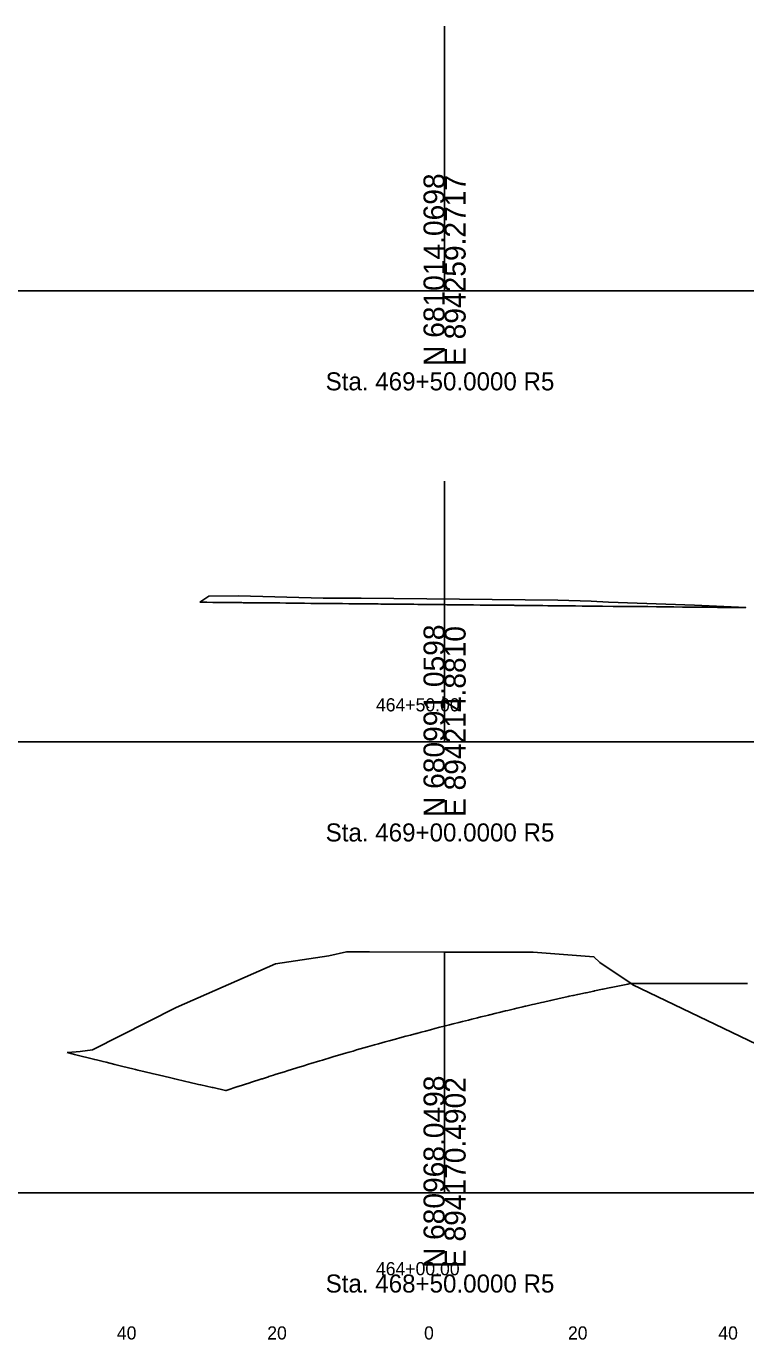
# Model space of a CAD drawing. Extents: x 21059 to 22955, y 6470 to 17494.
# Drawn here: x 21589.2 to 21684.9, y 9235.3 to 9410 of the extents above; entities that cross this region are included whole.
import ezdxf

# ---------------------------------------------------------------- set-up
doc = ezdxf.new("R2010")
doc.units = 0
for name, color, linetype in [('ASPHALT_19MM2', 7, 'Continuous'), ('Draft_XS_Text', 7, 'Continuous'), ('DTM CONTOURS_MAJOR', 7, 'Continuous'), ('SLOPE_STAKES_FILL', 7, 'Continuous'), ('X_PROFILES_1', 7, 'Continuous'), ('XS_SHEET_EW_TX_VOLUME', 7, 'Continuous')]:
    doc.layers.add(name, color=color, linetype=linetype)

msp = doc.modelspace()

# ---------------------------------------------------------------- linework, layer by layer
at = {"layer": 'DTM CONTOURS_MAJOR'}
for p, q in [((21644.84, 9374.84), (21644.84, 9410.02)), ((21494.84, 9374.84), (21644.84, 9374.84)), ((21644.84, 9374.84), (21794.84, 9374.84)), ((21644.84, 9314.84), (21644.84, 9349.53)), ((21494.84, 9314.84), (21644.84, 9314.84)), ((21644.84, 9314.84), (21794.84, 9314.84)), ((21644.84, 9254.84), (21644.84, 9286.89)), ((21494.84, 9254.84), (21644.84, 9254.84)), ((21644.84, 9254.84), (21794.84, 9254.84))]:
    msp.add_line(p, q, dxfattribs=at)
at = {"layer": 'XS_SHEET_EW_TX_VOLUME'}
for points in [[(21612.29, 9333.41), (21613.5, 9334.2), (21617.44, 9334.24), (21628.71, 9333.94), (21633.75, 9333.94), (21659.9, 9333.67), (21664.35, 9333.55), (21666.63, 9333.43), (21678.1, 9333.04), (21684.9, 9332.72), (21684.9, 9332.69), (21684.87, 9332.69), (21682.28, 9332.71), (21681.12, 9332.73), (21679.95, 9332.74), (21678.79, 9332.75), (21677.63, 9332.76), (21676.47, 9332.77), (21675.32, 9332.78), (21674.16, 9332.8), (21673.01, 9332.81), (21671.86, 9332.82), (21670.71, 9332.83), (21669.56, 9332.84), (21668.41, 9332.85), (21667.27, 9332.86), (21665.84, 9332.88), (21664.99, 9332.89), (21664.07, 9332.9), (21663.15, 9332.9), (21662.24, 9332.91), (21661.7, 9332.92), (21661.32, 9332.92), (21660.42, 9332.93), (21660.41, 9332.93), (21659.5, 9332.94), (21659.15, 9332.94), (21658.59, 9332.95), (21657.9, 9332.96), (21657.68, 9332.96), (21656.77, 9332.97), (21656.65, 9332.97), (21656.09, 9332.98), (21655.87, 9332.98), (21655.42, 9332.98), (21654.96, 9332.99), (21654.2, 9332.99), (21654.06, 9333), (21653.16, 9333), (21652.99, 9333.01), (21652.26, 9333.01), (21651.79, 9333.02), (21651.63, 9333.02), (21651.36, 9333.02), (21651, 9333.03), (21650.6, 9333.03), (21650.47, 9333.03), (21649.58, 9333.04), (21648.69, 9333.05), (21647.8, 9333.06), (21646.91, 9333.07), (21646.03, 9333.08), (21645.97, 9333.08), (21645.15, 9333.08), (21644.83, 9333.09), (21644.27, 9333.09), (21643.8, 9333.1), (21643.71, 9333.1), (21643.4, 9333.1), (21643.13, 9333.1), (21642.53, 9333.11), (21642.52, 9333.11), (21641.64, 9333.12), (21641.28, 9333.12), (21640.76, 9333.13), (21640.05, 9333.13), (21639.87, 9333.14), (21638.99, 9333.15), (21638.82, 9333.15), (21638.1, 9333.15), (21637.61, 9333.16), (21637.22, 9333.16), (21637.14, 9333.16), (21636.4, 9333.17), (21636.36, 9333.17), (21636.02, 9333.18), (21635.51, 9333.18), (21635.23, 9333.18), (21634.66, 9333.19), (21634.14, 9333.19), (21633.81, 9333.2), (21632.96, 9333.21), (21632.11, 9333.21), (21631.26, 9333.22), (21630.71, 9333.23), (21630.42, 9333.23), (21629.57, 9333.24), (21628.72, 9333.25), (21627.88, 9333.26), (21627.05, 9333.26), (21626.21, 9333.27), (21625.38, 9333.28), (21624.56, 9333.29), (21624.21, 9333.29), (21623.73, 9333.3), (21622.91, 9333.31), (21622.08, 9333.31), (21622.06, 9333.31), (21621.34, 9333.32), (21621.27, 9333.32), (21620.46, 9333.33), (21620.13, 9333.33), (21619.65, 9333.34), (21618.85, 9333.35), (21618.06, 9333.35), (21617.88, 9333.36), (21617.25, 9333.36), (21616.43, 9333.37), (21615.61, 9333.38), (21614.8, 9333.39), (21614.46, 9333.39), (21614, 9333.39), (21613.21, 9333.4), (21612.42, 9333.41)], [(21594.62, 9273.52), (21594.72, 9273.52), (21596.35, 9273.65), (21597.99, 9273.86), (21609.14, 9279.49), (21622.37, 9285.31), (21629.45, 9286.39), (21631.79, 9286.89), (21634.84, 9286.89), (21644.83, 9286.86), (21653.43, 9286.85), (21656.63, 9286.86), (21663.52, 9286.35), (21664.7, 9286.25), (21665.51, 9285.48), (21669.68, 9282.69), (21669.53, 9282.69), (21669.21, 9282.62), (21669.21, 9282.62), (21668.12, 9282.4), (21668.09, 9282.39), (21667.01, 9282.17), (21666.97, 9282.16), (21665.91, 9281.94), (21665.84, 9281.93), (21664.8, 9281.71), (21664.71, 9281.69), (21663.68, 9281.47), (21663.57, 9281.45), (21662.56, 9281.23), (21662.5, 9281.22), (21661.98, 9281.11), (21661.91, 9281.09), (21661.43, 9280.99), (21661.27, 9280.95), (21660.29, 9280.74), (21660.1, 9280.7), (21659.14, 9280.48), (21658.93, 9280.43), (21657.98, 9280.22), (21657.74, 9280.17), (21656.82, 9279.95), (21656.55, 9279.89), (21655.64, 9279.68), (21655.55, 9279.66), (21655.26, 9279.59), (21655.06, 9279.54), (21654.46, 9279.4), (21654.15, 9279.33), (21653.27, 9279.12), (21652.93, 9279.04), (21652.08, 9278.83), (21651.71, 9278.74), (21650.88, 9278.54), (21650.8, 9278.52), (21650.66, 9278.49), (21650.33, 9278.41), (21649.67, 9278.24), (21649.24, 9278.14), (21648.45, 9277.94), (21648, 9277.83), (21647.23, 9277.63), (21646.75, 9277.51), (21646, 9277.32), (21645.49, 9277.19), (21644.77, 9277.01), (21644.23, 9276.87), (21643.53, 9276.69), (21642.96, 9276.54), (21642.29, 9276.36), (21641.73, 9276.22), (21641.13, 9276.06), (21641.08, 9276.05), (21641.04, 9276.03), (21640.3, 9275.84), (21639.69, 9275.68), (21638.91, 9275.46), (21638.32, 9275.3), (21637.49, 9275.08), (21636.93, 9274.92), (21636.06, 9274.68), (21635.53, 9274.53), (21634.6, 9274.27), (21634.1, 9274.13), (21633.13, 9273.85), (21632.66, 9273.71), (21632.31, 9273.61), (21632.16, 9273.57), (21631.48, 9273.37), (21631.21, 9273.29), (21630.13, 9272.97), (21629.73, 9272.85), (21628.6, 9272.51), (21628.24, 9272.41), (21627.05, 9272.04), (21626.73, 9271.95), (21625.99, 9271.72), (21625.81, 9271.67), (21625.31, 9271.51), (21625.2, 9271.48), (21623.89, 9271.07), (21623.66, 9271), (21622.29, 9270.57), (21622.1, 9270.51), (21621.47, 9270.31), (21621.4, 9270.29), (21620.6, 9270.03), (21620.52, 9270.01), (21619.03, 9269.53), (21618.93, 9269.5), (21617.37, 9268.99), (21617.33, 9268.98), (21615.78, 9268.47), (21615.71, 9268.48), (21615.7, 9268.48), (21614.08, 9268.85), (21613.94, 9268.88), (21612.43, 9269.22), (21612.39, 9269.23), (21612.13, 9269.28), (21610.83, 9269.58), (21610.41, 9269.67), (21608.95, 9270.01), (21608.23, 9270.18), (21606.91, 9270.49), (21605.93, 9270.72), (21605, 9270.94), (21604.02, 9271.18), (21603.74, 9271.24), (21603.53, 9271.3), (21601.87, 9271.7), (21600.99, 9271.92), (21599.81, 9272.21), (21599.42, 9272.3), (21598.52, 9272.53), (21598.31, 9272.58), (21595.61, 9273.26), (21595.48, 9273.3)]]:
    msp.add_lwpolyline(points, close=True, dxfattribs=at)
msp.add_lwpolyline([(21685.12, 9282.69), (21684.84, 9282.69), (21684.08, 9282.69), (21683.75, 9282.69), (21683.04, 9282.69), (21682.65, 9282.69), (21681.99, 9282.69), (21681.55, 9282.69), (21680.94, 9282.69), (21680.49, 9282.69), (21679.98, 9282.69), (21679.93, 9282.69), (21679.87, 9282.69), (21679.32, 9282.69), (21678.83, 9282.69), (21678.22, 9282.69), (21677.78, 9282.69), (21677.12, 9282.69), (21676.73, 9282.69), (21676.01, 9282.69), (21675.67, 9282.69), (21674.89, 9282.69), (21674.61, 9282.69), (21674.49, 9282.69), (21674.13, 9282.69), (21674, 9282.69), (21673.54, 9282.69), (21672.64, 9282.69), (21672.47, 9282.69), (21671.49, 9282.69), (21671.39, 9282.69), (21670.35, 9282.69), (21670.3, 9282.69), (21670.3, 9282.69), (21670.15, 9282.69), (21670.13, 9282.69), (21669.68, 9282.69), (21669.9, 9282.54), (21689.67, 9273.04)], dxfattribs=at)

# ---------------------------------------------------------------- texts
at = {"layer": 'ASPHALT_19MM2'}
msp.add_text('X', height=0.12, dxfattribs=at).set_placement((21615.74, 9268.41))
at = {"layer": 'Draft_XS_Text'}
for s, p in [('  40  ', (21599.95, 9235.34)), ('  20  ', (21619.95, 9235.34)), ('  0  ', (21640.81, 9235.34)), ('  0  ', (21640.81, 9235.34)), ('  20  ', (21659.95, 9235.34)), ('  40  ', (21679.95, 9235.34))]:
    msp.add_text(s, height=1.75, dxfattribs=at).set_placement(p)
at = {"layer": 'DTM CONTOURS_MAJOR'}
for s, p in [('N 681014.0698', (21644.84, 9364.84)), ('E 894259.2717', (21647.64, 9364.84)), ('N 680991.0598', (21644.84, 9304.84)), ('E 894214.8810', (21647.64, 9304.84)), ('N 680968.0498', (21644.84, 9244.84)), ('E 894170.4902', (21647.64, 9244.84))]:
    msp.add_text(s, height=2.8, rotation=90, dxfattribs=at).set_placement(p)
at = {"layer": 'SLOPE_STAKES_FILL'}
for s, p in [('  464+50.00  ', (21634.41, 9318.89)), ('  464+00.00  ', (21634.41, 9243.89))]:
    msp.add_text(s, height=1.75, dxfattribs=at).set_placement(p)
at = {"layer": 'X_PROFILES_1'}
for s, p in [('Sta. 469+50.0000 R5', (21629.02, 9361.59)), ('Sta. 469+00.0000 R5', (21629.02, 9301.59)), ('Sta. 468+50.0000 R5', (21629.02, 9241.59))]:
    msp.add_text(s, height=2.4, dxfattribs=at).set_placement(p)

doc.saveas('drawing.dxf')
